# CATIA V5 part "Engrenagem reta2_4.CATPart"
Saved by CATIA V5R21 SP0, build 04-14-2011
Part number: Engrenagem reta2_4
Definition: Engrenagem reta2_4
Nomenclature: Engrenagem reta28
Source: Unknown
Bounding box of the stored display mesh (mm): x -2.788 to 2.788, y -2.787 to 2.787, z 0 to 1.7
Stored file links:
  C:\Users\beatr\OneDrive\Documents\UNB\2026_1\Pi1\Componentes eletronicos\Engrenagem reta2_4.CATPart
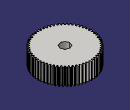
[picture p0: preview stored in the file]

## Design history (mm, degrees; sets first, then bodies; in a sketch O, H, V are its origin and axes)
Body1 "Solid1" (main body)
  Solid1: solid without history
